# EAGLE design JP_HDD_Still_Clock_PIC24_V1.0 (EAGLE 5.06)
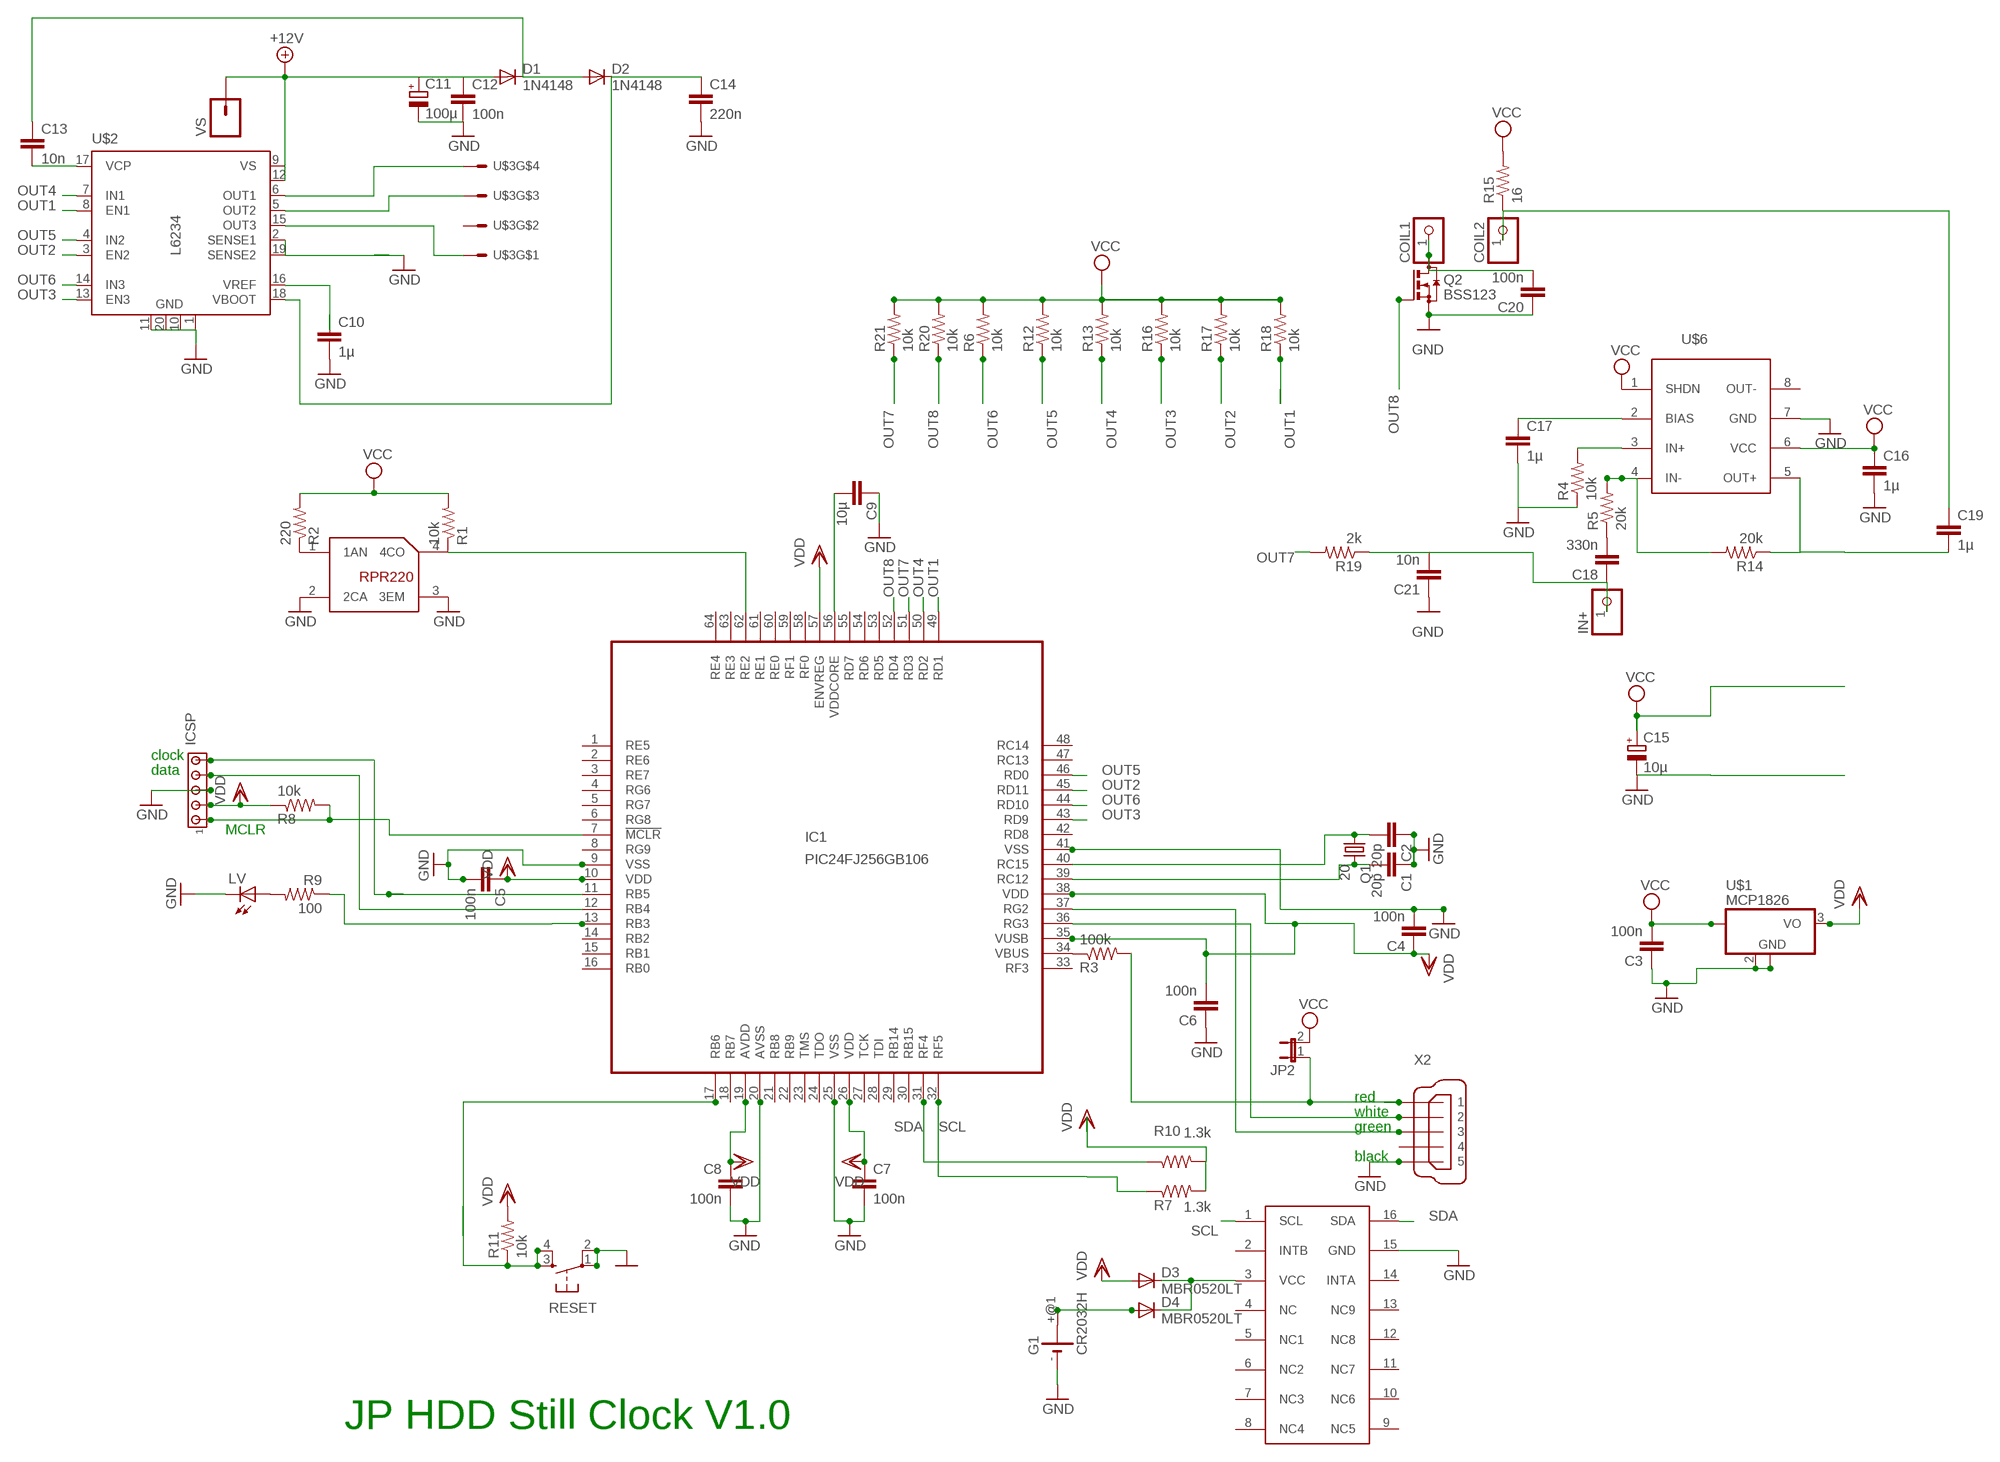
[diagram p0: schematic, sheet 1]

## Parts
C1  20p  C-EUC1206  [C1206]
C2  20p  C-EUC1206  [C1206]
C3  100n  C-EUC1206  [C1206]
C4  100n  C-EUC1206  [C1206]
C5  100n  C-EUC1206  [C1206]
C6  100n  C-EUC1206  [C1206]
C7  100n  C-EUC1206  [C1206]
C8  100n  C-EUC1206  [C1206]
C9  10µ  C-EUC1206  [C1206]
C10  1µ  C-EUC1206  [C1206]
C11  100µ  CPOL-EUE5-4  [E5-4]
C12  100n  C-EUC1206  [C1206]
C13  10n  C-EUC1206  [C1206]
C14  220n  C-EUC1206  [C1206]
C15  10µ  CPOL-EUB/3528-21R  [B/3528-21R]
C16  1µ  C-EUC1206  [C1206]
C17  1µ  C-EUC1206  [C1206]
C18  330n  C-EUC1206  [C1206]
C19  1µ  C-EUC1206  [C1206]
C20  100n  C-EUC1206  [C1206]
C21  10n  C-EUC1206  [C1206]
COIL1  PINHD-1X1  [1X01]
COIL2  PINHD-1X1  [1X01]
D1  1N4148  1N4148DO35-7  [DO35-7]
D2  1N4148  1N4148DO35-7  [DO35-7]
D3  MBR0520LT  [SOD123]
D4  MBR0520LT  [SOD123]
G1  CR2032H  [CR2032H]
IC1  PIC24FJ256GB106  [TQFP64-10X10]
ICSP  MTA05-100  [10X05MTA]
IN+  PINHD-1X1  [1X01]
JP2  JP1E  [JP1]
LV  LED3MM  [LED3MM]
Q1  20  CRYSTALHC49S  [HC49/S]
Q2  BSS123  [SOT23]
R1  10k  RESISTOR1206  [1206]
R2  220  RESISTOR1206  [1206]
R3  100k  RESISTOR1206  [1206]
R4  10k  RESISTOR1206  [1206]
R5  20k  RESISTOR1206  [1206]
R6  10k  RESISTOR1206  [1206]
R7  1.3k  RESISTOR1206  [1206]
R8  10k  RESISTOR1206  [1206]
R9  100  RESISTOR1206  [1206]
R10  1.3k  RESISTOR1206  [1206]
R11  10k  RESISTOR1206  [1206]
R12  10k  RESISTOR1206  [1206]
R13  10k  RESISTOR1206  [1206]
R14  20k  RESISTOR1206  [1206]
R15  16  RESISTOR1206  [1206]
R16  10k  RESISTOR1206  [1206]
R17  10k  RESISTOR1206  [1206]
R18  10k  RESISTOR1206  [1206]
R19  2k  RESISTOR1206  [1206]
R20  10k  RESISTOR1206  [1206]
R21  10k  RESISTOR1206  [1206]
RESET  TAC_SWITCHPTH  [TACTILE-PTH]
U$1  MCP1826  [SOT223]
U$2  L6234  [POWERSO-20]
U$3  52746-1  [52746-1]
U$4  DS1337C  [SO16L]
U$5  RPR220  [RPR220]
U$6  MAX9716  [UMAX8-THERMAL]
VS  M01PTH_LONGPAD  [1X01_LONGPAD]
X2  MINI-USB-32005-201  [32005-201]

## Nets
+12V: C11.+ C12.1 D1.A U$2.9(VS) U$2.12(VS) VS.1
GND: C1.1 C2.1 C3.1 C4.2 C5.2 C6.1 C7.2 C8.2 C9.1 C10.2 C11.- C12.2 C14.2 C15.- C16.2 C17.2 C20.1 C21.1 G1.- IC1.9(VSS) IC1.20(AVSS) IC1.25(VSS) IC1.41(VSS) ICSP.3 LV.K(C) Q2.2(S) R4.1 RESET.1 RESET.2 U$1.2(GND) U$1.4(PADGND) U$2.1(GND) U$2.2(SENSE1) U$2.10(GND) U$2.11(GND) U$2.19(SENSE2) U$2.20(GND) U$5.2(2CA) U$5.3(3EM) U$6.7(GND) X2.5
N$2: IC1.62(RE2) R1.1 U$5.4(4CO)
N$3: D3.C D4.C U$4.3(VCC)
N$5: IC1.7(!MCLR) ICSP.1 R8.2
N$6: IC1.34(VBUS) R3.1
N$7: C2.2 IC1.40(RC15) Q1.1
N$8: JP2.1 R3.2 X2.1
N$10: D4.A G1.+@1(+)
N$11: U$2.6(OUT1) U$3.4
N$12: U$2.5(OUT2) U$3.3
N$13: R2.1 U$5.1(1AN)
N$14: C19.1 COIL2.1 R15.1
N$17: IC1.13(RB3) R9.1
N$18: C17.1 U$6.2(BIAS)
N$21: U$2.15(OUT3) U$3.1
N$22: IC1.37(RG2) X2.3
N$25: C10.1 U$2.16(VREF)
N$27: R4.2 U$6.3(IN+)
N$28: C13.1 D1.C D2.A
N$31: C9.2 IC1.56(VDDCORE)
N$33: LV.A R9.2
N$34: IC1.17(RB6) R11.1 RESET.3 RESET.4
N$37: C13.2 U$2.17(VCP)
N$38: C14.1 D2.C U$2.18(VBOOT)
N$41: R5.2 R14.2 U$6.4(IN-)
N$42: C18.2 R5.1
N$46: C19.2 R14.1 U$6.5(OUT+)
N$48: C18.1 C21.2 IN+.1 R19.1
N$49: C20.2 COIL1.1 Q2.3(D)
N$61: C1.2 IC1.39(RC12) Q1.2
N$70: IC1.36(RG3) X2.2
OUT1: IC1.49(RD1) R18.1 U$2.8(EN1)
OUT2: IC1.45(RD11) R17.1 U$2.3(EN2)
OUT3: IC1.43(RD9) R16.1 U$2.13(EN3)
OUT4: IC1.50(RD2) R13.1 U$2.7(IN1)
OUT5: IC1.46(RD0) R12.1 U$2.4(IN2)
OUT6: IC1.44(RD10) R6.1 U$2.14(IN3)
OUT7: IC1.51(RD3) R19.2 R21.1
OUT8: IC1.52(RD4) Q2.1(G) R20.1
RB4: IC1.12(RB4) ICSP.4
RB5: IC1.11(RB5) ICSP.5
SCL: IC1.32(RF5) R7.1 U$4.1(SCL)
SDA: IC1.31(RF4) R10.1 U$4.16(SDA)
VCC: C3.2 C15.+ C16.1 JP2.2 R1.2 R2.2 R6.2 R12.2 R13.2 R15.2 R16.2 R17.2 R18.2 R20.2 R21.2 U$1.1(VI) U$6.1(SHDN) U$6.6(VCC)
VDD: C4.1 C5.1 C6.2 C7.1 C8.1 D3.A IC1.10(VDD) IC1.19(AVDD) IC1.26(VDD) IC1.35(VUSB) IC1.38(VDD) IC1.57(ENVREG) ICSP.2 R7.2 R8.1 R10.2 R11.2 U$1.3(VO)
Unconnected: G1.+ IC1.1(RE5) IC1.2(RE6) IC1.3(RE7) IC1.4(RG6) IC1.5(RG7) IC1.6(RG8) IC1.8(RG9) IC1.14(RB2) IC1.15(RB1) IC1.16(RB0) IC1.18(RB7) IC1.21(RB8) IC1.22(RB9) IC1.23(TMS) IC1.24(TDO) IC1.27(TCK) IC1.28(TDI) IC1.29(RB14) IC1.30(RB15) IC1.33(RF3) IC1.42(RD8) IC1.47(RC13) IC1.48(RC14) IC1.53(RD5) IC1.54(RD6) IC1.55(RD7) IC1.58(RF0) IC1.59(RF1) IC1.60(RE0) IC1.61(RE1) IC1.63(RE3) IC1.64(RE4) U$3.2 U$4.2(INTB) U$4.4(NC) U$4.5(NC1) U$4.6(NC2) U$4.7(NC3) U$4.8(NC4) U$4.9(NC5) U$4.10(NC6) U$4.11(NC7) U$4.12(NC8) U$4.13(NC9) U$4.14(INTA) U$6.8(OUT-) X2.4

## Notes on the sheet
- clock
- data
- MCLR
- red
- white
- green
- black
- JP HDD Still Clock V1.0

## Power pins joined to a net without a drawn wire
GND: U$4.15(GND)

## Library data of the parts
C1-C9 C18 C20 C21 = resistor:C-EU: CAPACITOR, European symbol
C10 C12-C14 C16 C17 C19 = rcl:C-EU: CAPACITOR, European symbol
C11 C15 = rcl:CPOL-EU: POLARIZED CAPACITOR, European symbol
COIL1 COIL2 IN+ = pinhead:PINHD-1X1: PIN HEADER
D1 D2 = diode:1N4148: DIODE
D3 D4 = diode:MBR0520LT: SCHOTTKY BARRIER RECTIFIER
G1 = battery:CR2032H: LI BATTERY Varta
IC1 = microchip:PIC24FJ256GB106: PIC24FJ256GB106 edit this description Auto generated by make-symbol-device-package-bsdl.ulp Rev. 25 Source: PIC24FJ256GB106.bsd
ICSP = con-amp:MTA05-100: AMP connector
JP2 = jumper:JP1E: JUMPER
LV = led:LED: LED
Q1 = crystal:CRYSTAL: CRYSTAL
Q2 = transistor-small-signal:BSS123: N-CHANNEL MOS FET
R1-R21 = SparkFun:RESISTOR: Resistor
RESET = SparkFun:TAC_SWITCH: Momentary Switch Button commonly used for reset or general input. Spark Fun Electronics SKU : COM-00097
U$1 = linear:MCP1826: Microchip linear regulator low dropout 1000mA SOT223 package
U$2 = st-microelectronics:L6234: L6234 Three phase motor driver
U$3 = con-molex:52746-1: FPC connector ZIF for SMT 1mm pitch 4 pins
U$4 = maxim:DS1337C: DS1337 Real Time Clock Calendar RTCC
U$5 = allegro:RPR220: RPR220 Reflective photosensor (photoreflector)
U$6 = maxim:MAX9716: MAX9716 Low-Cost, Mono, 1.4W BTL Audio Power Amplifiers
VS = SparkFun:M01: Header 1
X2 = con-cypressindustries:MINI-USB-: MINI USB-B Conector Source: www.cypressindustries.com

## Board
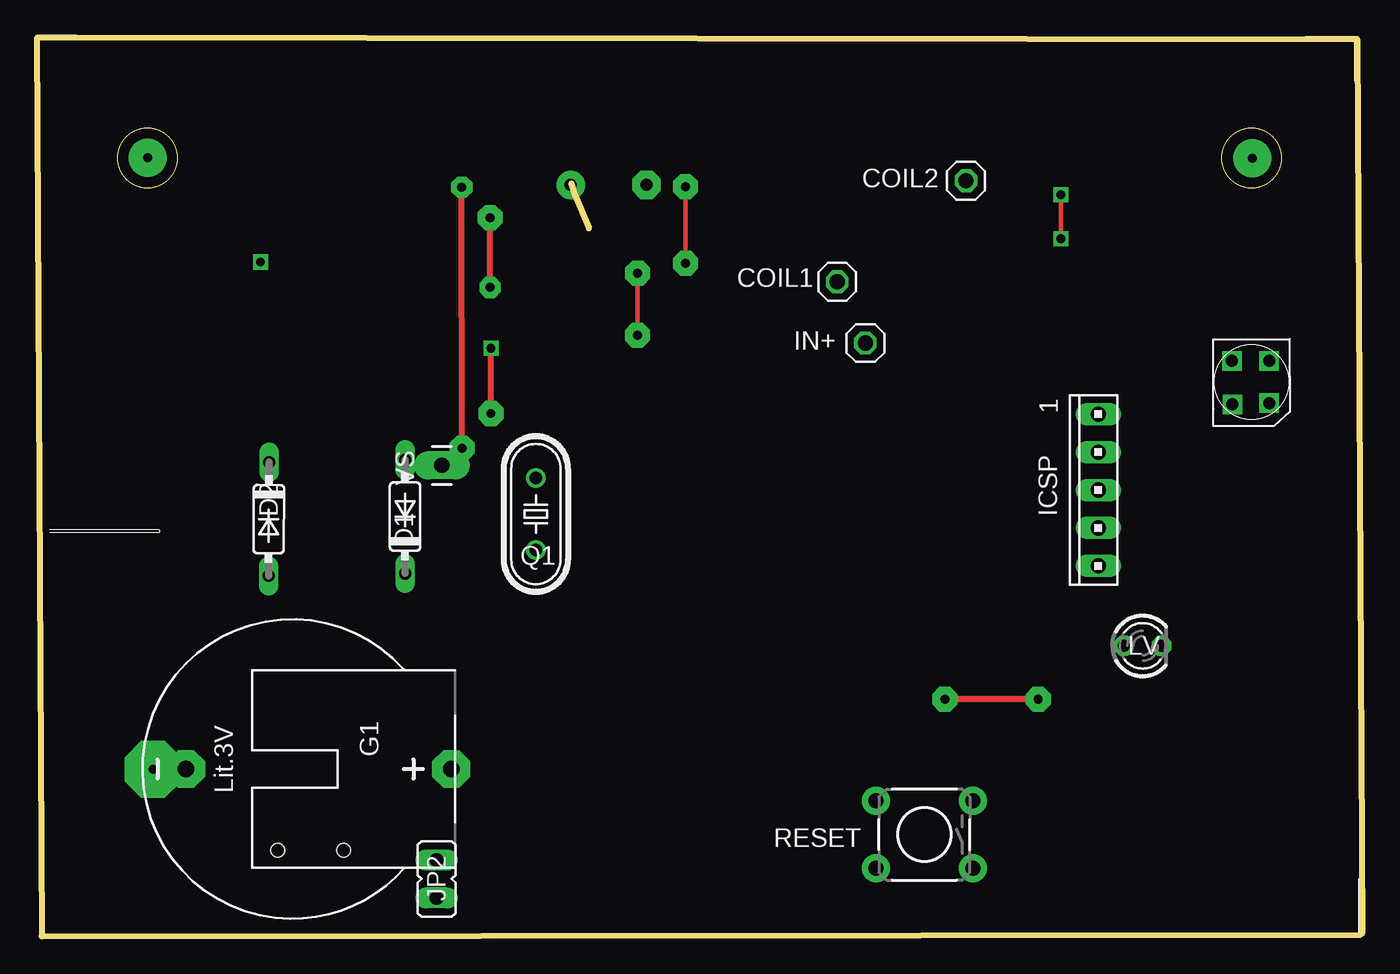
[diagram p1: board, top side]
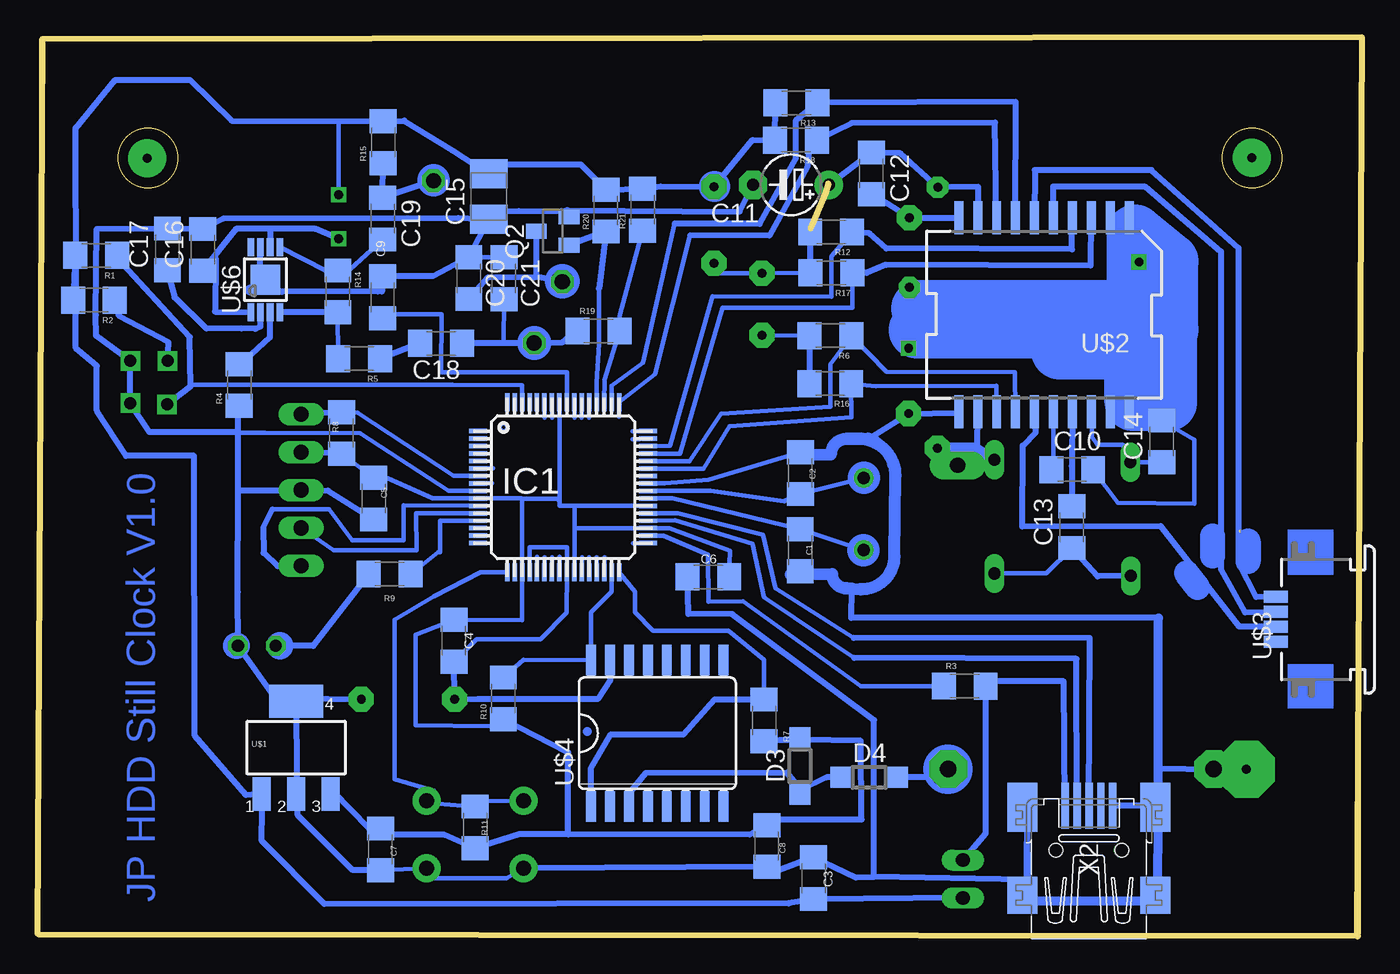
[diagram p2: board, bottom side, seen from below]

Size 88.81 x 60.25 mm. Coordinates in mm from the lower left corner, seen from the top.
Outline: 88.81,0.21 88.47,60.12 0,60.25 0.32,0
Outline: 0.28,0.02 88.7,0.13
Outline: 35.78,50.46 36.01,49.73 36.97,47.44
Outline: 8.13,27.07 arc180 8.13,27.25
Outline: 88.64,60.16 0.14,60.16 0.14,0.16 88.64,0.16 88.64,60.16
Outline: circle at 81.39,52.16 radius 2
Outline: circle at 7.39,52.16 radius 2
Copper layers (1*16): Top 0.035mm / dielectric 1.5mm / Bottom 0.035mm
Design rules "default": minimum track width 10mil, minimum drill 24mil, track to track 8mil, track to pad 8mil, pad to pad 8mil, via to via 8mil, smd to smd 8mil, copper to edge 40mil, drill to drill 8mil, minimum pad ring 10mil, minimum via ring 8mil, stop-mask expansion 4mil, vias tented up to drill 0mil, thermal gap 10mil

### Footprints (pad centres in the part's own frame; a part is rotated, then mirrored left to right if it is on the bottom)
C1206 = smd 1.6 x 1.8: 1 -1.4,0; 2 1.4,0
E5-4 = drill 0.813 pad 1.905 round: + -2.54,0 | drill 0.813 pad 1.905 octagon: - 2.54,0
B/3528-21R = smd 1.95 x 2.5: + 1.525,0; - -1.525,0
1X01 = drill 1.016 octagon: 1 0,0
DO35-7 = drill 0.813 long: A 3.81,0; C -3.81,0
SOD123 = smd 1.4 x 1.4: A 1.9,0; C -1.9,0
CR2032H = drill 1.118 pad 2.54 octagon: + 0,10.795; +@1 0,10.795; - 0,-6.985
TQFP64-10X10 = smd 1.2 x 0.3: 1 -5.7,3.75; 2 -5.7,3.25; 3 -5.7,2.75; 4 -5.7,2.25; 5 -5.7,1.75; 6 -5.7,1.25; 7 -5.7,0.75; 8 -5.7,0.25; 9 -5.7,-0.25; 10 -5.7,-0.75; 11 -5.7,-1.25; 12 -5.7,-1.75; 13 -5.7,-2.25; 14 -5.7,-2.75; 15 -5.7,-3.25; 16 -5.7,-3.75; 33 5.7,-3.75; 34 5.7,-3.25; 35 5.7,-2.75; 36 5.7,-2.25; 37 5.7,-1.75; 38 5.7,-1.25; 39 5.7,-0.75; 40 5.7,-0.25; 41 5.7,0.25; 42 5.7,0.75; 43 5.7,1.25; 44 5.7,1.75; 45 5.7,2.25; 46 5.7,2.75; 47 5.7,3.25; 48 5.7,3.75 | smd 0.3 x 1.2: 17 -3.75,-5.7; 18 -3.25,-5.7; 19 -2.75,-5.7; 20 -2.25,-5.7; 21 -1.75,-5.7; 22 -1.25,-5.7; 23 -0.75,-5.7; 24 -0.25,-5.7; 25 0.25,-5.7; 26 0.75,-5.7; 27 1.25,-5.7; 28 1.75,-5.7; 29 2.25,-5.7; 30 2.75,-5.7; 31 3.25,-5.7; 32 3.75,-5.7; 49 3.75,5.7; 50 3.25,5.7; 51 2.75,5.7; 52 2.25,5.7; 53 1.75,5.7; 54 1.25,5.7; 55 0.75,5.7; 56 0.25,5.7; 57 -0.25,5.7; 58 -0.75,5.7; 59 -1.25,5.7; 60 -1.75,5.7; 61 -2.25,5.7; 62 -2.75,5.7; 63 -3.25,5.7; 64 -3.75,5.7
10X05MTA = drill 1.016 long: 1 5.08,0; 2 2.54,0; 3 0,0; 4 -2.54,0; 5 -5.08,0
JP1 = drill 0.914 long: 1 0,-1.27; 2 0,1.27
LED3MM = drill 0.813 octagon: A -1.27,0; K 1.27,0
HC49/S = drill 0.813 round: 1 -2.413,0; 2 2.413,0
SOT23 = smd 1 x 1.4: 1 -0.95,-1.1; 2 0.95,-1.1; 3 0,1.1
1206 = smd 1.6 x 1.8: 1 -1.4,0; 2 1.4,0
TACTILE-PTH = drill 1.016 pad 1.88 round: 1 -3.251,2.261; 2 3.251,2.261; 3 -3.251,-2.261; 4 3.251,-2.261
SOT223 = smd 1.219 x 2.235: 1 -2.311,-3.099; 2 0,-3.099; 3 2.311,-3.099 | smd 3.6 x 2.2: 4 0,3.099
POWERSO-20 = smd 0.6 x 2.2: 1 -5.715,-6.5; 2 -4.445,-6.5; 3 -3.175,-6.5; 4 -1.905,-6.5; 5 -0.635,-6.5; 6 0.635,-6.5; 7 1.905,-6.5; 8 3.175,-6.5; 9 4.445,-6.5; 10 5.715,-6.5; 11 5.715,6.5; 12 4.445,6.5; 13 3.175,6.5; 14 1.905,6.5; 15 0.635,6.5; 16 -0.635,6.5; 17 -1.905,6.5; 18 -3.175,6.5; 19 -4.445,6.5; 20 -5.715,6.5
52746-1 = smd 0.8 x 1.6: 1 -0.487,3.532; 2 -1.501,3.532; 3 0.516,3.542; 4 1.519,3.542
SO16L = smd 0.66 x 2.032: 1 -4.445,-4.902; 2 -3.175,-4.902; 3 -1.905,-4.902; 4 -0.635,-4.902; 5 0.635,-4.902; 6 1.905,-4.902; 7 3.175,-4.902; 8 4.445,-4.902; 9 4.445,4.902; 10 3.175,4.902; 11 1.905,4.902; 12 0.635,4.902; 13 -0.635,4.902; 14 -1.905,4.902; 15 -3.175,4.902; 16 -4.445,4.902
RPR220 = drill 0.8 square: 1 0,0; 2 0,2.5; 3 2.834,2.496; 4 2.905,0.034
UMAX8-THERMAL = smd 0.45 x 1.2: 1 -0.975,-2.175; 2 -0.325,-2.175; 3 0.325,-2.175; 4 0.975,-2.175; 5 0.975,2.175; 6 0.325,2.175; 7 -0.325,2.175; 8 -0.975,2.175 | smd 2 x 2: TH 0,0
1X01_LONGPAD = drill 1.016 pad 1.88 long: 1 0,0
32005-201 = smd 3.1 x 0.5: 1 3,1.6; 2 3,0.8; 3 3,0; 4 3,-0.8; 5 3,-1.6 | smd 2.5 x 2: M1 -3,-4.45; M2 -3,4.45 | smd 3.3 x 2: M3 2.9,4.45; M4 2.9,-4.45 | hole 0.9: 0,2.2; 0,-2.2

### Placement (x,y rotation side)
C1  37.67,25.88 90 bottom
C2  37.66,31.05 270 bottom
C3  36.77,3.91 270 bottom
C4  60.88,19.81 270 bottom
C5  66.25,29.34 270 bottom
C6  43.83,24.09 0 bottom
C7  65.81,5.84 270 bottom
C8  39.9,6.06 270 bottom
C9  65.66,42.83 270 bottom
C10  19.44,31.28 0 bottom
C11  38.29,50.36 180 bottom
C12  32.9,51.12 270 bottom
C13  19.46,27.43 90 bottom
C14  13.44,33.17 90 bottom
C15  58.54,49.58 90 bottom
C16  77.72,46 90 bottom
C17  80.09,46.04 90 bottom
C18  61.74,39.74 180 bottom
C19  65.66,48.1 270 bottom
C20  59.88,44.11 270 bottom
C21  57.53,44.1 270 bottom
COIL1  53.62,43.86 0 top
COIL2  62.25,50.64 0 top
D1  24.65,28.13 90 top
D2  15.52,27.97 269.7 top
D3  37.68,11.43 90 bottom
D4  33.04,10.66 0 bottom
G1  16.95,11.22 270 top
IC1  53.56,30.1 0 bottom
ICSP  71.12,29.91 90 top
IN+  55.5,39.76 0 top
JP2  26.76,3.85 180 top
LV  74.09,19.47 0 top
Q1  33.42,28.3 270 top
Q2  54.26,47.26 90 bottom
R1  84.86,45.63 180 bottom
R2  85.01,42.64 180 bottom
R3  26.64,16.77 359.8 bottom
R4  75.26,36.95 90 bottom
R5  67.24,38.71 180 bottom
R6  35.64,40.26 180 bottom
R7  40.09,14.47 270 bottom
R8  68.42,33.73 90 bottom
R9  65.19,24.28 180 bottom
R10  57.57,15.95 270 bottom
R11  59.46,7.3 270 bottom
R12  35.6,47.2 180 bottom
R13  37.92,55.86 180 bottom
R14  68.66,43.22 270 bottom
R15  65.62,53.21 90 bottom
R16  35.65,37.04 180 bottom
R17  35.58,44.46 180 bottom
R18  37.96,53.36 180 bottom
R19  51.18,40.56 0 bottom
R20  50.69,48.64 90 bottom
R21  48.24,48.69 90 bottom
RESET  59.46,6.83 180 top
U$1  71.45,12.65 0 bottom
U$2  21.33,41.66 180 bottom
U$3  2.26,21.24 90 bottom
U$4  47.24,13.62 0 bottom
U$5  80.07,38.56 270 top
U$6  73.52,44.01 0 bottom
VS  27.12,31.57 90 top
X2  18.32,5.76 90 bottom

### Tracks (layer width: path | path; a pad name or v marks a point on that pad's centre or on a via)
+12V  (via drill 0.6 pad 1.42, 0.6 pad 1.68)
  Top 0.406: v28.47,32.72 v28.45,50.21
  Bottom 0.305: D1.A 25.23,32.22 25.8,32.7
  Bottom 0.406: 25.8,32.7 U$2.12 | U$2.9 25.73,50.22 v28.45,50.21 30.95,52.47 C12.1 C11.+ | VS.1 28.38,32.61 v28.47,32.72
  Bottom 0.813: v28.47,32.72 25.91,32.68 25.23,32.22
GND  (via drill 0.6, 0.6 pad 1.42, 0.6 pad 1.68)
  Top 0.406: v30.35,43.49 v30.35,48.16 | v30.4,35.04 v30.4,39.41 | v67.08,15.9 v60.82,15.9
  Bottom 0.305: IC1.20 55.81,26.08 53.31,26.08 IC1.25 53.32,21.7 55.09,19.92 59.35,19.92 C4.2 | C2.1 39.89,31.77 43.83,30.61 46.73,30.36 IC1.41 | IC1.9 61.22,29.85 67.18,33.72 73.54,33.74 75.34,33.74 75.34,33.78 | U$2.20 C14.2 11.25,33.29 11.25,28.98 16.38,29.07 C10.2 | RESET.2 57.35,3.9 62.23,3.9 RESET.1 C7.2 | C20.1 C21.1
  Bottom 0.406: 33.72,33.34 33.09,33.29 | 34.52,23.31 34.49,23.31 | 75.1,19.54 75.21,19.82 | 75.35,29.9 75.37,23.09 LV.K 72.76,15.85 U$1.4 71.43,15.95 | C5.2 69.33,29.88 ICSP.3 75.35,29.9 | U$2.20 15.7,35.11 U$2.19 16.88,41.81 | U$2.1 U$2.2 16.88,41.81 | 30.35,41.86 16.88,41.81 | 30.35,41.86 30.24,41.89 | U$2.10 v30.35,48.16 31.83,49.1 C12.2 | 30.35,41.86 v30.35,43.49 | 30.35,41.86 30.4,41.53 v30.4,39.41 | 33.11,33.36 v30.4,35.04 27.21,35.08 U$2.11 | C11.- 41.74,48.56 53.27,48.66 53.7,48.6 | 34.21,23.3 34.24,21.35 13.66,21.35 | 13.67,8.77 X2.5 | 22.38,2.35 22.48,8.96 22.52,3.81 32.73,4.01 | 32.73,4.01 32.76,3.97 33.9,3.94 C3.1 39.11,4.45 C8.2 RESET.2 | 13.67,11.29 G1.- | 50.35,18.17 50.38,17.16 51.19,15.94 59.29,15.92 v60.82,15.9 C4.2 | 32.73,4.01 32.72,14.49 42.23,21.6 45.17,21.61 C6.1 | 71.37,10.49 71.43,15.95 | 71.37,10.49 U$1.2 | 53.7,48.6 56.52,48.61 58.31,48.59 C15.- | U$6.7 73.87,46.16 73.87,44.28 72.98,43.39 72.92,43.39 72.88,43.43 72.42,43.18 65.7,43.22 | 65.7,43.22 65.98,43.2 | 75.34,33.74 75.33,35.04 R4.1 | 65.7,43.22 C9.1 62.29,44.24 C20.1 C15.- | C15.- 60.57,48.14 76.32,48.11 77.76,47.39 C16.2 C17.2 84.81,47.42 84.88,41.64 84.86,40.26 U$5.2 U$5.3 81.27,33.8 75.34,33.78 75.35,29.9 | 53.7,48.6 Q2.2 | 71.37,10.49 71.35,8.11 67.66,4.45 C7.2 | 71.43,15.95 v67.08,15.9
  Bottom 0.409: 50.35,18.17 U$4.15
  Bottom 0.61: 13.66,21.35 13.67,11.29 13.67,8.77 13.7,2.36 22.38,2.35
  Bottom 0.813: C2.1 arc90 37.83,32.25 35.62,32.29 arc90 34.52,33.34 | 34.52,33.34 33.72,33.34 arc90 31.28,30.87 31.35,25.46 arc90 33.53,23.27 33.65,23.27 34.21,23.3 34.52,23.31 arc90 35.53,24.28 38.31,24.24 arc-90 C1.1 | 34.52,33.34 33.11,33.36 32.73,33.26 | LV.K 75.1,19.54
N$2
  Bottom 0.305: IC1.62 56.32,36.93 60.98,36.96 78.47,36.96 U$5.4
  Bottom 0.406: U$5.4 78.53,36.86 78.58,40.16 83.45,45.43 R1.1
N$3
  Bottom 0.406: 38.55,10.98 D3.C | 38.55,10.98 48.02,10.95 49.11,9.62 U$4.3 | D4.C 35.91,10.66 37.6,9.84 38.55,10.98
N$4
  Bottom 0.305: 49.8,35.4 49.8,34.81
N$5
  Bottom 0.305: IC1.7 60.9,30.85 67.32,35.09 R8.2
  Bottom 0.406: R8.2 ICSP.1
N$6
  Bottom 0.305: IC1.34 46.88,26.86 46.85,26.86 43.85,25.58 43.82,22.42 41.52,22.45 33.58,16.75 R3.1
N$7
  Bottom 0.305: IC1.40 43.67,29.85 38.76,29.15 C2.2 Q1.1
N$8
  Bottom 0.406: X2.1 20,17.09 25.2,17.11 R3.2 25.24,6.88 JP2.1
N$9
  Bottom 0.305: 51.81,35.39 51.81,34.77
N$10
  Bottom 0.406: G1.+@1 28.13,10.66 D4.A
N$11
  Bottom 0.406: U$3.4 7.1,22.74 8.28,25.02 8.28,46.12 14.13,51.35 21.95,51.35 U$2.6
N$12
  Bottom 0.406: U$2.5 20.7,50.25 14.57,50.25 9.46,45.88 9.47,24.6 7.85,21.72 U$3.3
N$13
  Bottom 0.406: U$5.1 80.01,39.81 83.31,41.57 R2.1
N$14
  Bottom 0.406: R15.1 65.67,49.65 C19.1 COIL2.1
N$15  (via drill 0.6 pad 3.81)
  other vias: 7.76,11.2
N$16
  Bottom 0.305: 54.81,35.3 54.81,34.75
N$17
  Bottom 0.305: IC1.13 61.82,27.85 61.82,25.76 61.95,25.76 R9.1
N$18
  Bottom 0.406: U$6.2 73.86,40.86 74.18,40.71 75.13,40.74 77.46,40.73 79.61,42.83 C17.1
N$19
  Bottom 0.305: 58.86,31.36 58.27,31.36
N$20
  Bottom 0.305: 54.31,35.33 54.31,35.3 54.3,34.74
N$21
  Bottom 0.406: U$2.15 21.89,33.78 22.75,32.89 22.79,27.46 13.5,27.49 8.25,20.76 U$3.1
N$22
  Bottom 0.305: IC1.37 45.86,28.36 40.17,26.9 39.31,23.32 34.09,20
  Bottom 0.406: X2.3 18.26,19.98 34.09,20
N$23
  Bottom 3.81: 29.82,40.65 12.89,40.66 12.88,45.24 15.23,47.14 15.23,42.07 29.66,42.07 21.67,41.63 20.29,40.91 20.29,39.24 15.37,39.24 12.98,39.82 12.98,35.76 15.37,35.76 15.37,38.88
N$24
  Bottom 0.305: 52.31,35.54 52.31,34.77
N$25
  Bottom 0.305: C10.1 20.7,32.11 U$2.16
N$26
  Bottom 0.305: 53.8,34.14 53.81,34.13 53.81,35.24
N$27
  Bottom 0.406: 75.06,38.31 75.31,38.39 R4.2 74.83,38.65 73.2,40.14 U$6.3
N$28
  Bottom 0.305: C13.1 21.17,24.32 D1.C
  Bottom 0.406: D2.A 17.74,24.13 C13.1
N$30
  Bottom 0.305: 52.81,35.39 52.81,35.3 52.81,34.74
N$31
  Bottom 0.305: IC1.56 53.31,37.8 61.74,37.8 61.72,41.68 65.04,41.67 C9.2
N$32  (via drill 0.6 pad 2.54)
  other vias: 7.4,52.18
N$33
  Bottom 0.406: LV.A 70.3,19.46 R9.2
N$34
  Bottom 0.305: RESET.4 59.86,9.07 R11.1 61.99,8.89 RESET.3 62.19,8.96 62.23,9.78 64.86,10.52 64.86,21.23 62.19,22.79 59.1,24.42 IC1.17
N$35  (via drill 0.6 pad 2.54)
  other vias: 81.43,52.15
N$36
  Bottom 0.305: 58.73,30.35 58.32,30.36
N$37
  Bottom 0.406: U$2.17 19.47,31.54 C13.2
N$38
  Bottom 0.305: U$2.18 18.14,33.5 17.75,32.95 16.06,32.95 D2.C C14.1
N$39
  Bottom 0.305: 48.32,26.36 48.33,26.35 48.88,26.35
N$40
  Bottom 0.305: 50.8,24.9 50.8,25.42
N$41
  Bottom 0.305: R5.2 R14.2
  Bottom 0.406: R5.2 68.61,38.93 | R14.2 U$6.4
N$42
  Bottom 0.406: C18.2 R5.1
N$43
  Bottom 0.305: 51.31,24.85 51.31,25.41
N$44
  Bottom 0.305: 51.81,24.86 51.81,25.41
N$45
  Bottom 0.305: 52.32,24.89 52.31,24.9 52.31,25.4
N$46
  Bottom 0.305: C19.2 67.87,44.67 R14.1 69.43,44.61 U$6.5
N$47
  Bottom 0.305: 53.82,24.87 53.8,24.9 53.8,25.45
N$48
  Bottom 0.305: 57.55,39.75 C21.2
  Bottom 0.406: 56.13,39.76 IN+.1 | 56.13,39.76 57.55,39.75 C18.1 | R19.1 52.74,40.57 53.65,39.8 56.13,39.76
N$49
  Bottom 0.406: COIL1.1 55.34,44.2 | 55.34,44.2 55.48,44.14 58.6,44.17 C20.2 | 55.34,44.2 Q2.3
N$50
  Bottom 0.305: 54.32,24.86 54.32,25.41
N$51
  Bottom 0.305: 54.82,24.85 54.81,24.86 54.81,25.42
N$52
  Bottom 0.305: 55.32,24.84 55.31,24.85 55.31,25.43
N$53  (via drill 0.6)
  other vias: 14.96,45.19
N$54
  Bottom 0.305: 48.34,33.88 48.39,33.86 48.92,33.86
N$55
  Bottom 0.305: 48.43,33.33 48.89,33.33
N$56
  Bottom 1.676: 7.64,26.27 7.64,26.48 7.64,26.27 | 7.64,26.27 7.64,25.13
N$57
  Bottom 1.676: 11.78,24.34 11.03,23.37
N$58  (via drill 0.6)
  other vias: 16.13,5.78
N$59  (via drill 0.6)
  other vias: 20.52,5.77
N$60
  Bottom 1.676: 10.03,26.84 10.03,25.48
N$61
  Bottom 0.305: IC1.39 47.8,29.36 46.24,29.36 C1.2 Q1.2
N$70
  Bottom 0.305: IC1.36 46.07,27.88 40.88,26.33 40.09,22.73 34.06,18.67
  Bottom 0.406: X2.2 19.16,18.59 34.06,18.67
OUT1
  Bottom 0.305: R18.1 37.06,53.21 | 45.05,46.97 47.4,37.67 IC1.49
  Bottom 0.406: U$2.8 24.62,54.53 34.2,54.5 R18.1 | 45.05,46.97 39.74,46.95 37.19,51.56 37.06,53.21
OUT2
  Bottom 0.305: R17.1 34.16,42.11 42.88,42.13 45.72,32.35 IC1.45
  Bottom 0.406: R17.1 33.2,44.46 31.91,44.99 18.19,44.96 U$2.3
OUT3
  Bottom 0.305: U$2.13 24.5,36.9 32.59,36.85 R16.1 34.24,34.78 42.4,34.19 44.17,31.35 IC1.43
OUT4
  Bottom 0.305: IC1.50 50.33,35.8 50.3,35.8 50.31,36.89 48.21,38.43 46.09,47.76
  Bottom 0.406: U$2.7 23.21,55.93 R13.1 37.98,54.64 37.98,52.12 40.39,47.74 46.09,47.76
OUT5
  Bottom 0.305: R12.1 35.58,45.58 35.58,42.88 43.55,42.88 46.38,32.87 IC1.46
  Bottom 0.406: U$2.4 19.45,46.04 31.9,46.11 33.02,47.11 R12.1
OUT6
  Bottom 0.305: U$2.14 23.26,37.8 31.91,37.82 R6.1 35.63,38.36 35.63,35.5 42.99,35.03 45.08,31.85 IC1.44
OUT7
  Bottom 0.305: IC1.51 50.8,37.3 R19.2 49.78,41.57 R21.1
OUT8
  Bottom 0.305: 51.17,43.41 51.17,39.73 51.31,37.11 IC1.52
  Bottom 0.406: Q2.1 R20.1 51.17,43.41
RB4
  Bottom 0.305: IC1.12 63.41,28.35 63.39,25.89 68.94,25.87 ICSP.4
RB5
  Bottom 0.305: IC1.11 64.24,28.9 64.24,26.53 67.71,26.53 69.25,28.63 73.06,28.62
  Bottom 0.406: 73.06,28.62 73.65,27.42 73.64,25.7 72.7,24.82 ICSP.5
SCL
  Bottom 0.305: IC1.32 48.73,23.1 48.74,21.74 47.54,20.48 42.47,20.49 40.09,18.53 R7.1
  Bottom 0.406: U$4.1 51.72,11.27 50.4,13.51 45.5,13.52 43.4,15.87 R7.1
SDA
  Bottom 0.305: IC1.31 50.32,23.1 51.69,21.73 U$4.16 56.21,18.53 R10.1
VCC  (via drill 0.6, 0.6 pad 1.68)
  Top 0.305: v40.24,44.44 v40.22,40.28 | v43.44,50.24 v43.46,45.11 | v68.6,49.69 v68.6,46.75
  Bottom 0.305: v40.22,40.28 R6.2 | R17.2 v40.24,44.44 43.11,44.44 v43.46,45.11 | 59.4,50.62 58.91,51.73 | v68.6,49.69 68.6,54.63 R15.2
  Bottom 0.406: R6.2 R16.2 | R17.2 R12.2 | R13.2 R18.2 40.87,53.38 v43.44,50.24 47.02,50.26 R21.2 R20.2 52.38,51.73 58.91,51.73 | JP2.2 C3.2 38.44,2.22 69.56,2.17 73.76,6.4 73.7,10.42 U$1.1 74.81,9.46 78.24,13.46 78.29,32.2 82.85,32.2 84.82,35.24 84.82,38.23 86.22,39.43 R1.2 R2.2 86.21,43.43 86.24,54.17 83.58,57.39 78.59,57.39 75.78,54.66 R15.2 64.21,54.66 60.98,52.66 C15.+ 59.4,50.62 59.56,51.82 | U$6.1 76.89,41.87 76.85,45.38 C16.1 75.49,47.41 73.21,47.41 | 73.21,47.41 U$6.6 | 73.21,47.41 70.17,47.41 v68.6,46.75
VDD
  Bottom 0.305: 52.8,27.36 IC1.26 | 52.8,27.36 IC1.35 46.44,27.35 42.37,25.83 C6.2 | 52.8,28.84 52.8,28.85 | 52.8,28.84 52.8,27.36 | 52.8,28.85 IC1.38 | 55.79,29.34 55,29.34 53.82,29.34 53.8,28.84 | 55.79,29.34 56.35,29.35 IC1.10 62.3,29.35 65.32,30.7 C5.1 R8.1 | R11.2 60.15,6.37 | IC1.57 53.8,35.8 53.8,28.84 | 53.8,28.84 52.8,28.84 | 52.8,28.84 52.8,28.85 | 55.79,29.34 56.3,29.31 IC1.19 56.3,21.2 60.29,21.22 C4.1 63.45,20.23 63.45,14.15 58.47,14.1 R10.2 | ICSP.2 71.17,32.53
  Bottom 0.406: R8.1 ICSP.2 | D3.A R7.2 37.62,13.19 33.6,13.11 33.56,7.83 39.9,7.83 C8.1 | 53.22,12.32 R10.2 | U$1.3 68.93,9.65 66.58,7.25 C7.1 64.94,6.8 61.5,6.8 R11.2
  Bottom 0.409: R11.2 56.47,6.85 53.22,6.84 | 53.22,6.84 41.05,6.82 C8.1 | 53.22,6.84 53.22,12.32
(copper drawn outside any net)
  shapes: Bottom circle x12

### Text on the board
Bottom: JP HDD Still Clock V1.0
tPlace: 1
